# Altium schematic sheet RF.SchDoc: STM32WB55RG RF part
size A4; Author: PhA; SheetNumber: 3; SheetTotal: 6
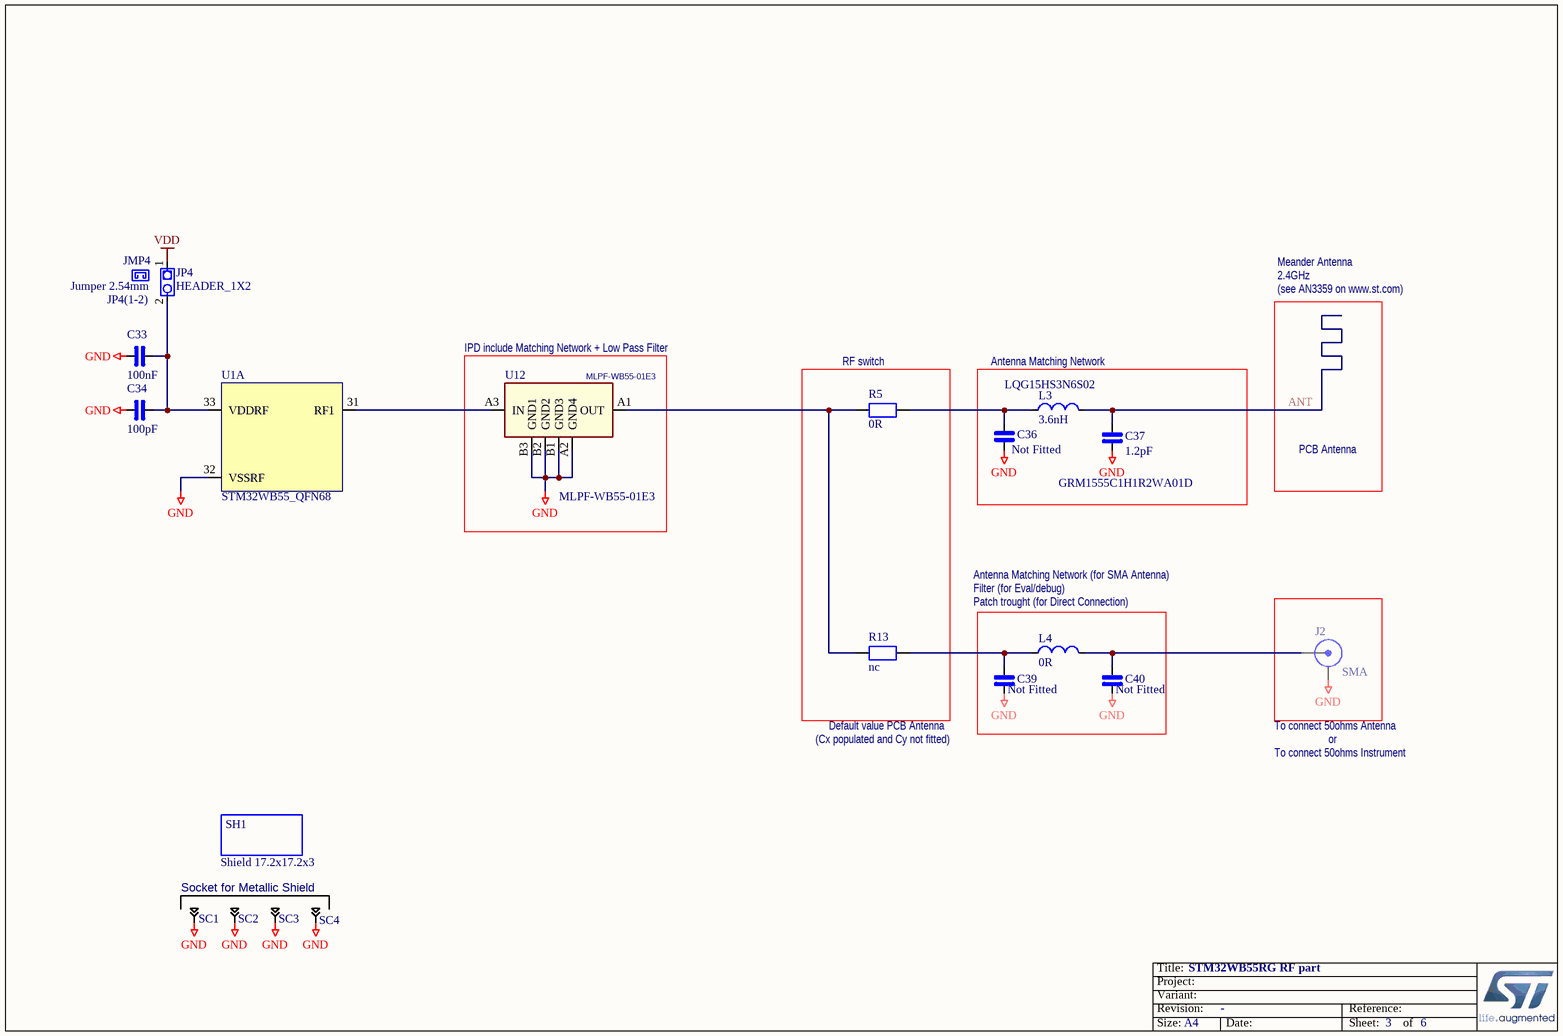
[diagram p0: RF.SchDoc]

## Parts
C33  100nF  [0402_CAP_NPOL]
C34  100pF  [0402_CAP_NPOL]
C36  Fitted: Not Fitted  [0402_CAP_NPOL]
C37  1.2pF  Ref: GRM1555C1H1R2WA01D  [0402_CAP_NPOL]
C39  Fitted: Not Fitted  [0402_CAP_NPOL]
C40  Fitted: Not Fitted  [0402_CAP_NPOL]
J2  SMA  [SMA_T_9.52_NF]
JMP4  Jumper 2.54mm  default: JP4(1-2)  [Jumper 2.54mm BLACK]
JP4  HEADER_1X2  [Header M 1x2x2.54 TH V]
L3  3.6nH  Ref: LQG15HS3N6S02  [0402_COIL]
L4  0R  [0402_COIL]
R5  0R  [0402_RES]
R13  nc  [0402_RES]
SC1  Shield Clip_A 3.9x1.1x1.28  [Shield Clip_A 3.9x1.1x1.28]  (value not drawn)
SC2  Shield Clip_A 3.9x1.1x1.28  [Shield Clip_A 3.9x1.1x1.28]  (value not drawn)
SC3  Shield Clip_A 3.9x1.1x1.28  [Shield Clip_A 3.9x1.1x1.28]  (value not drawn)
SC4  Shield Clip_A 3.9x1.1x1.28  [Shield Clip_A 3.9x1.1x1.28]  (value not drawn)
SH1  Shield 17.2x17.2x3  [Shield 17.2x17.2x3]
U1  STM32WB55_QFN68  [VFQFPN68_8x8x0.1_p0.4]  (part A of 5)
U12  MLPF-WB55-01E3  [ST_CSP650x58P2x3_160x100x42]

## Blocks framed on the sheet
IPD include Matching Network + Low Pass Filter: U12
RF switch: R5 R13
Antenna Matching Network: C36 C37 L3

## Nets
GND: C33.1 C34.1 C36.2 C37.1 C39.1 C40.1 J2.2(Y) SC1.1 SC2.1 SC3.1 SC4.1 U1.32(VSSRF) U12.A2(GND4) U12.B1(GND3) U12.B2(GND2) U12.B3(GND1)
VDD: JP4.1
ANT: C37.2 L3.2
NetC33_2: C33.2 C34.2 JP4.2 U1.33(VDDRF)
NetC36_1: C36.1 L3.1 R5.2
NetC39_2: C39.2 L4.1 R13.2
NetC40_2: C40.2 J2.1(X) L4.2
NetR5_1: R5.1 R13.1 U12.A1(OUT)
NetU1_31: U1.31(RF1) U12.A3(IN)

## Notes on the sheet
- Meander Antenna
- 2.4GHz
- (see AN3359 on www.st.com)
- PCB Antenna
- Antenna Matching Network (for SMA Antenna)
- Filter (for Eval/debug)
- Patch trought (for Direct Connection)
- (near C39) (Cx populated and Cy not fitted)
- Default value PCB Antenna
- To connect 50ohms Antenna
- To connect 50ohms Instrument
- or
- Socket for Metallic Shield

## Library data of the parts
C33 C34 C36 C37 C39 C40 = CAP_NPOL: Capacitor_not polarized
JP4 = HEADER_1X2_L
L3 L4 = INDUCTOR_SMD_STDL
R5 R13 = RES: Resistor
SC1-SC4 = Shield Clip_A 3.9x1.1x1.28: Harwin S0951-46R
SH1 = Shield
U1 = STM32WBxx_QFN68
U12 = MCD-02059: 2.4 GHz low pass filter matched to STM32WBx5Cx/Rx; Part_Type: IC; Manufacturer: STMICROELECTRONICS; ECCN_US: EAR99; ECCN_EU: NEC; Provided_By: SUBCO with ST control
